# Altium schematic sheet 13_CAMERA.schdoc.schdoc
size 302 x 215 mm; Symbol: Sheet_A4; Device: Sheet_A4; @Project Name: Avaota Pi A; Company: YuzukiHD; Version: 1.0; @Page No: 13; @Page Count: 13; @Update Date: 2024-02-27; Comment: GloomyGhost
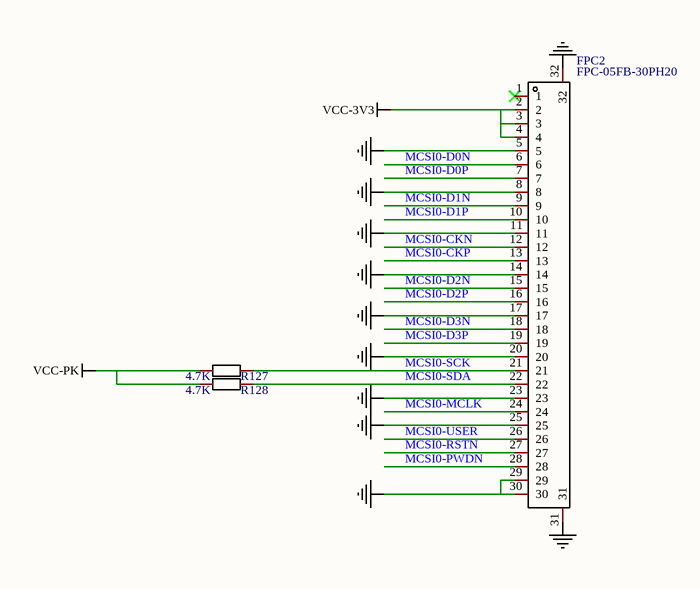
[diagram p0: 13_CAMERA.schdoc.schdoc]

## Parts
FPC2  FPC-05FB-30PH20  [FPC-SMD_30P-P0.50_FPC-05FB-30PH20]
R127  4.7K  [r0201 nsk]
R128  4.7K  [r0201 nsk]

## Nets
NetFPC2_5: FPC2.5 FPC2.8 FPC2.11 FPC2.14 FPC2.17 FPC2.20 FPC2.23 FPC2.25 FPC2.29 FPC2.30 FPC2.31 FPC2.32
VCC-3V3: FPC2.2 FPC2.3 FPC2.4
VCC-PK: R127.1 R128.1
MCSI0-CKN: FPC2.12
MCSI0-CKP: FPC2.13
MCSI0-D0N: FPC2.6
MCSI0-D0P: FPC2.7
MCSI0-D1N: FPC2.9
MCSI0-D1P: FPC2.10
MCSI0-D2N: FPC2.15
MCSI0-D2P: FPC2.16
MCSI0-D3N: FPC2.18
MCSI0-D3P: FPC2.19
MCSI0-MCLK: FPC2.24
MCSI0-PWDN: FPC2.28
MCSI0-RSTN: FPC2.27
MCSI0-SCK: FPC2.21 R127.2
MCSI0-SDA: FPC2.22 R128.2
MCSI0-USER: FPC2.26

Not connected (* = marked no-connect by the designer): FPC2 1*

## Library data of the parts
FPC2 = FPC-05FB-30PH20: Manufacturer: XUNPU(讯普); Add into BOM: yes; Locking Feature: 翻盖式; Number of Contacts: 30P; Pitch: 0.5mm; FFC, FCB Thickness: 0.3mm; Description: 锁定特性:翻盖式;触点类型:双侧触点/上下接;触点数量:30P;间距:0.5mm;安装类型:卧贴;工作温度范围:-25℃~+85℃;
R127 R128 = Res_0201: Symbol: 电阻; Convert to PCB: yes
